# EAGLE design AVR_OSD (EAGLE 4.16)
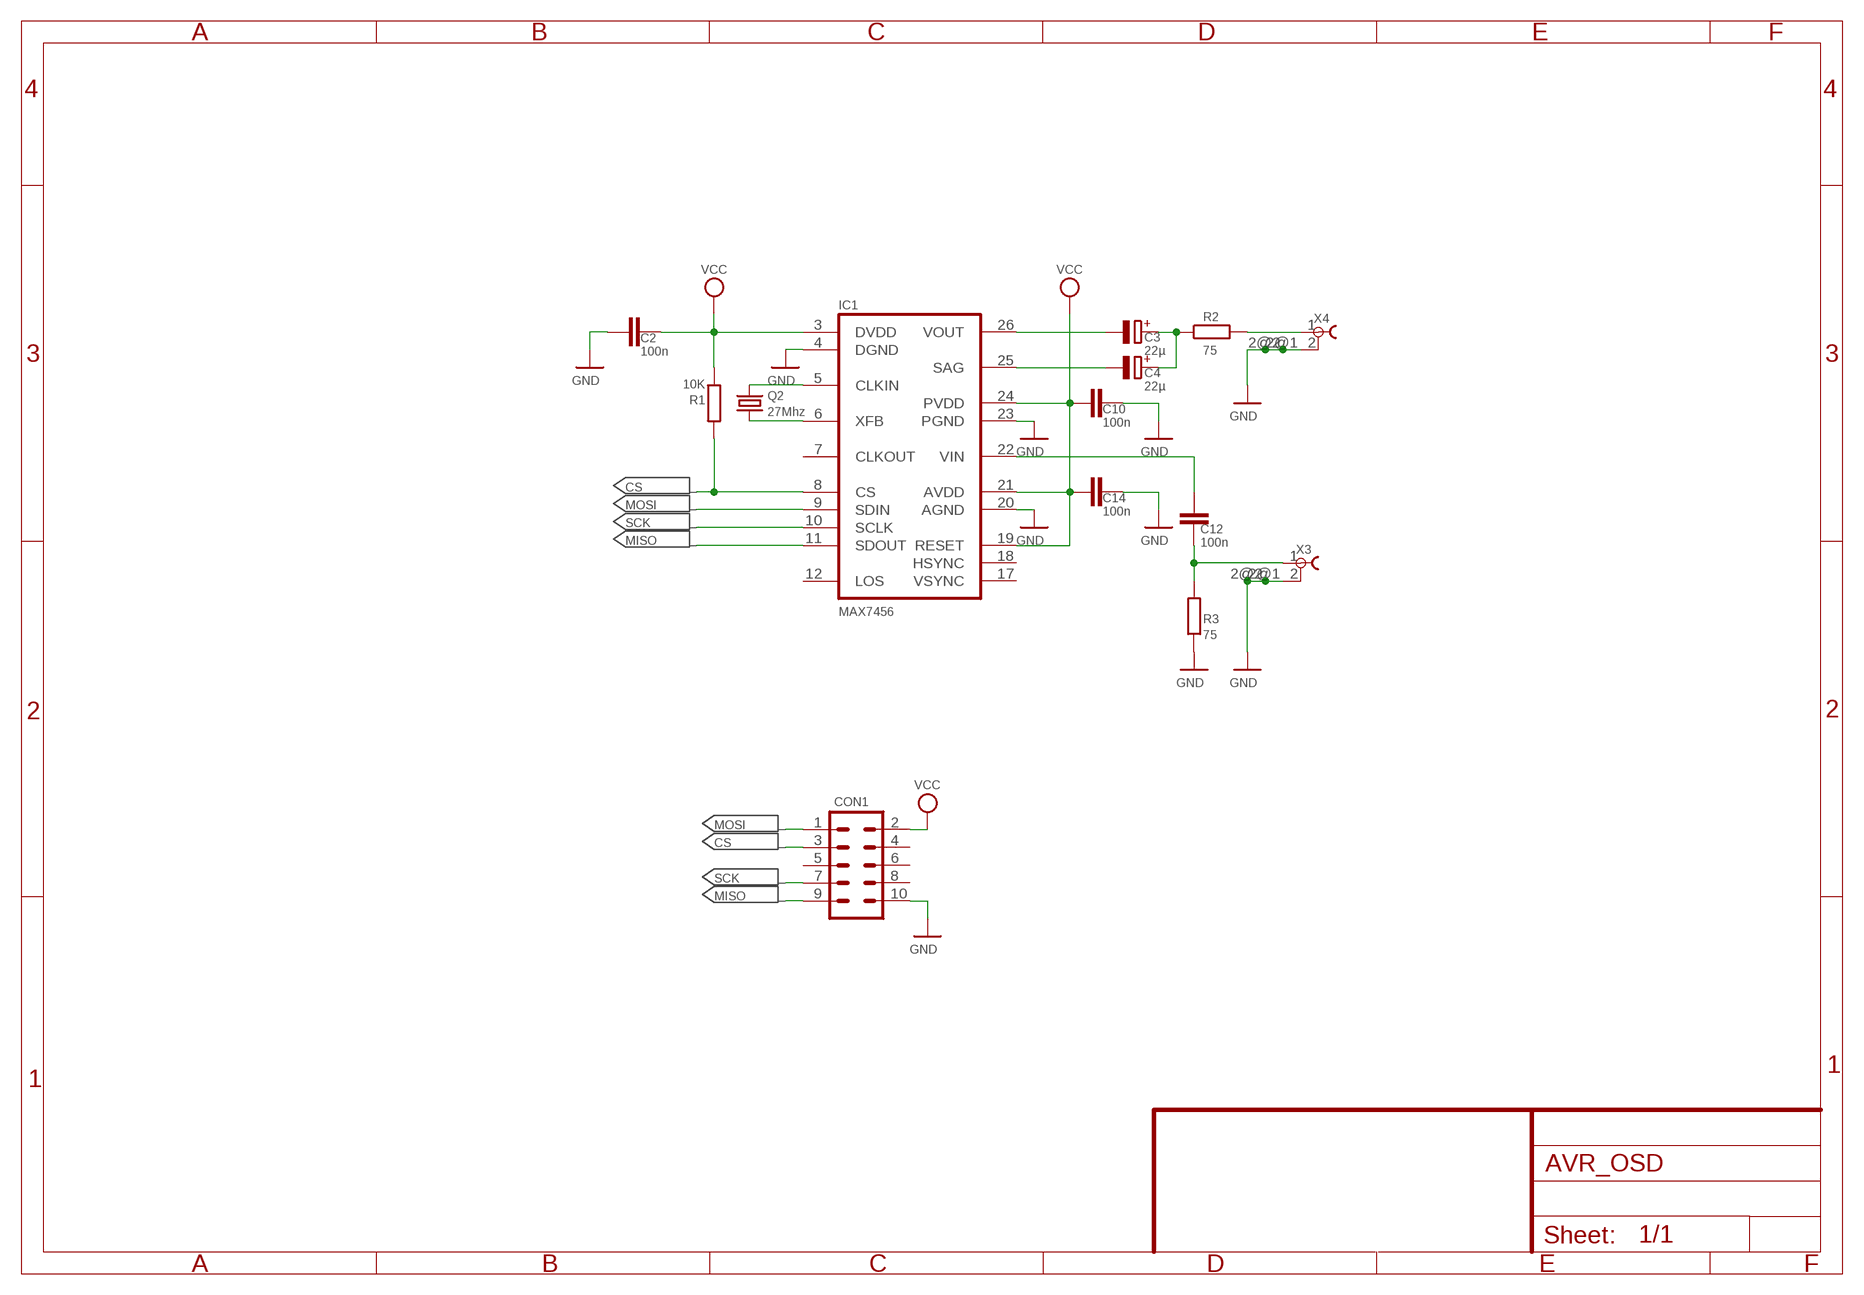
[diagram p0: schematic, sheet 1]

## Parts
C2  100n  C-EUC0805  [C0805]
C3  22µ  CPOL-EUSMCC  [SMC_C]
C4  22µ  CPOL-EUSMCC  [SMC_C]
C10  100n  C-EUC0805  [C0805]
C12  100n  C-EUC0805  [C0805]
C14  100n  C-EUC0805  [C0805]
CON1  ML10  [ML10]
IC1  MAX7456  [TSSOP28]
Q2  27Mhz  CRYSTALHC49S  [HC49/S]
R1  10K  R-EU_M0805  [M0805]
R2  75  R-EU_M0805  [M0805]
R3  75  R-EU_M0805  [M0805]
X3  TOBU3  [TOBU3]
X4  TOBU3  [TOBU3]

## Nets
CS: CON1.3 IC1.8(CS) R1.2
GND: C2.1 C10.2 C14.1 CON1.10 IC1.4(DGND) IC1.20(AGND) IC1.23(PGND) R3.1 X3.2 X3.2@1 X3.2@2 X4.2 X4.2@1 X4.2@2
MISO: CON1.9 IC1.11(SDOUT)
MOSI: CON1.1 IC1.9(SDIN)
N$24: C3.- IC1.26(VOUT)
N$27: C4.- IC1.25(SAG)
N$28: C3.+ C4.+ R2.1
N$29: R2.2 X4.1
N$30: C12.1 IC1.22(VIN)
N$33: C12.2 R3.2 X3.1
N$38: IC1.5(CLKIN) Q2.2
N$41: IC1.6(XFB) Q2.1
SCK: CON1.7 IC1.10(SCLK)
VCC: C2.2 C10.1 C14.2 CON1.2 IC1.3(DVDD) IC1.19(RESET) IC1.21(AVDD) IC1.24(PVDD) R1.1
Unconnected: CON1.4 CON1.5 CON1.6 CON1.8 IC1.7(CLKOUT) IC1.12(LOS) IC1.17(VSYNC) IC1.18(HSYNC)

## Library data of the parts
C2 C10 C12 C14 = rcl:C-EU: CAPACITOR, European symbol
C3 C4 = rcl:CPOL-EU: POLARIZED CAPACITOR, European symbol
CON1 = con-harting-ml:ML10: HARTING
IC1 = max7456:MAX7456
Q2 = crystal:CRYSTAL: CRYSTAL
R1-R3 = rcl:R-EU_: RESISTOR, European symbol
X3 X4 = con-hirschmann:TOBU3: Female Cinch CONNECTOR

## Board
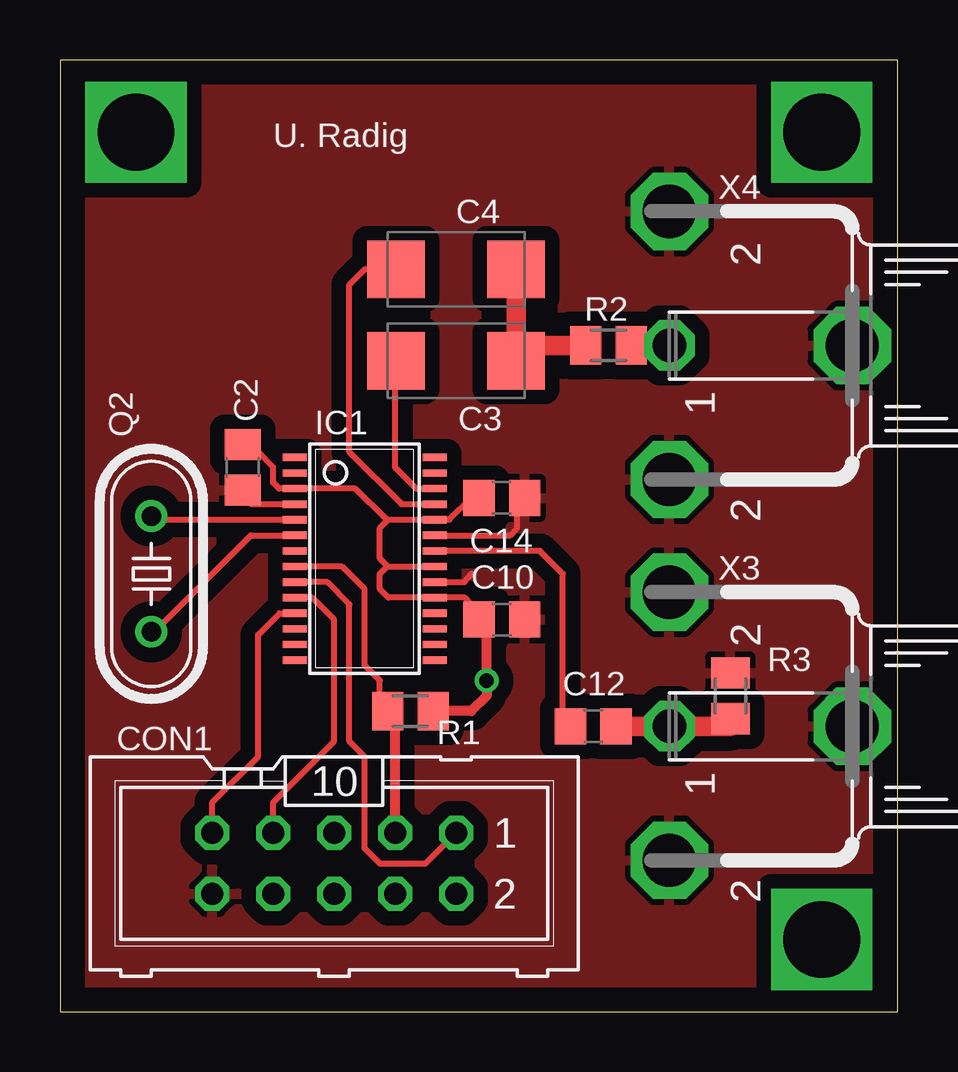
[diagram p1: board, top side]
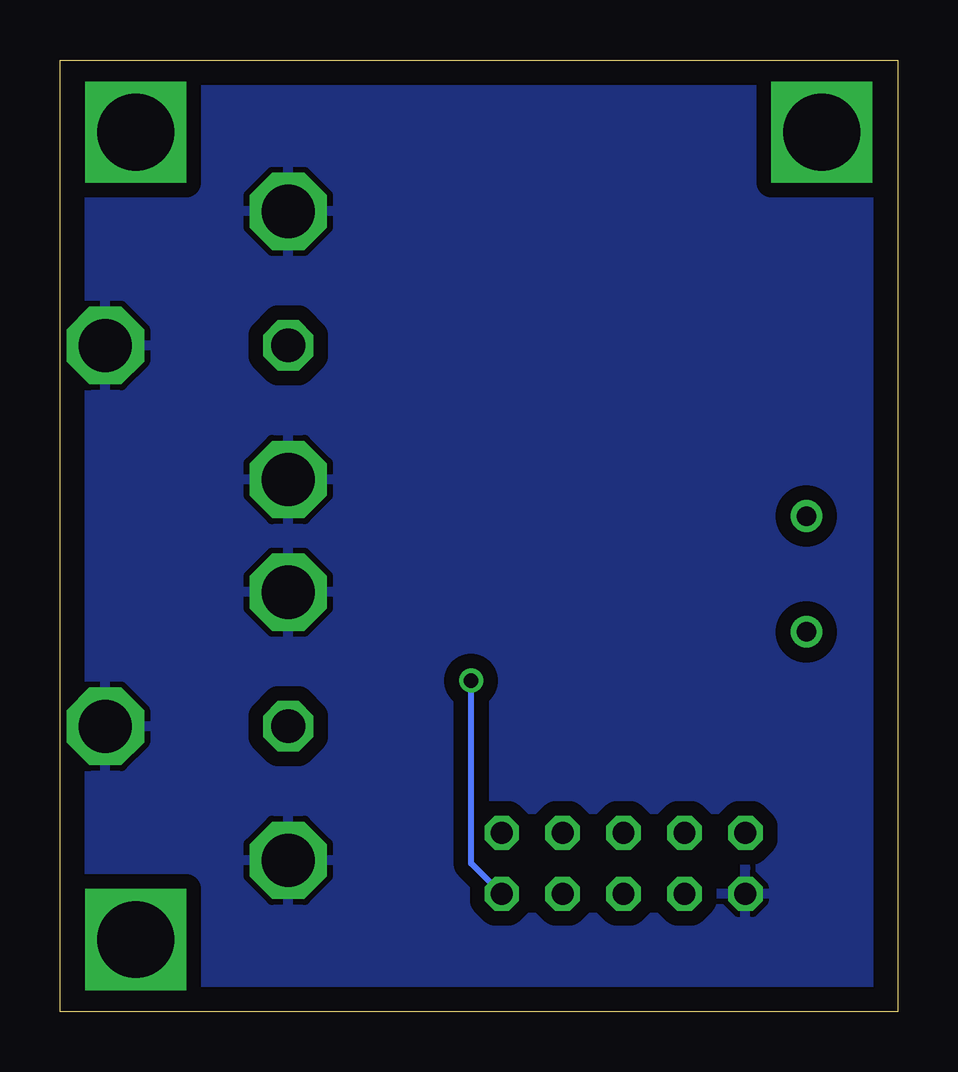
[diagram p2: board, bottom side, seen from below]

Size 34.9 x 39.68 mm. Coordinates in mm from the lower left corner, seen from the top.
Outline: 0,0 34.9,0 34.9,39.68 0,39.68 0,0
Copper layers (1*16): Top 0.035mm / dielectric 1.5mm / Bottom 0.035mm
Design rules "default": minimum track width 10mil, minimum drill 24mil, track to track 8mil, track to pad 8mil, pad to pad 8mil, via to via 8mil, smd to smd 8mil, copper to edge 40mil, drill to drill 8mil, minimum pad ring 10mil, minimum via ring 8mil, stop-mask expansion 4mil, vias tented up to drill 0mil, thermal gap 10mil

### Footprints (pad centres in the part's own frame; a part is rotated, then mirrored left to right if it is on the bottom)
C0805 = smd 1.3 x 1.5: 1 -0.95,0; 2 0.95,0
SMC_C = smd 2.4 x 2.4: + -2.5,0; - 2.5,0
ML10 = drill 0.914 octagon: 1 -5.08,-1.27; 2 -5.08,1.27; 3 -2.54,-1.27; 4 -2.54,1.27; 5 0,-1.27; 6 0,1.27; 7 2.54,-1.27; 8 2.54,1.27; 9 5.08,-1.27; 10 5.08,1.27
TSSOP28 = smd 0.305 x 0.991: 1 -4.225,-2.918; 2 -3.575,-2.918; 3 -2.925,-2.918; 4 -2.275,-2.918; 5 -1.625,-2.918; 6 -0.975,-2.918; 7 -0.325,-2.918; 8 0.325,-2.918; 9 0.975,-2.918; 10 1.625,-2.918; 11 2.275,-2.918; 12 2.925,-2.918; 13 3.575,-2.918; 14 4.225,-2.918; 15 4.225,2.918; 16 3.575,2.918; 17 2.925,2.918; 18 2.275,2.918; 19 1.625,2.918; 20 0.975,2.918; 21 0.325,2.918; 22 -0.325,2.918; 23 -0.975,2.918; 24 -1.625,2.918; 25 -2.275,2.918; 26 -2.925,2.918; 27 -3.575,2.918; 28 -4.225,2.918
HC49/S = drill 0.813 round: 1 -2.413,0; 2 2.413,0
M0805 = smd 1.3 x 1.6: 1 -0.95,0; 2 0.95,0
TOBU3 = drill 1.397 octagon: 1 0,-2.54 | drill 2.21 octagon: 2 5.588,-2.54; 2@1 -5.588,-2.54; 2@2 0,5.08

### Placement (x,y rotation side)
C2  7.62,22.7 90 top
C3  16.51,27.14 180 top
C4  16.51,30.95 180 top
C10  18.41,16.35 0 top
C12  22.22,11.9 0 top
C14  18.41,21.43 180 top
CON1  11.42,6.18 180 top
IC1  12.69,18.89 270 top
Q2  3.81,18.25 90 top
R1  14.6,12.54 180 top
R2  22.86,27.78 0 top
R3  27.94,13.17 270 top
X3  27.94,11.9 270 top
X4  27.94,27.78 270 top

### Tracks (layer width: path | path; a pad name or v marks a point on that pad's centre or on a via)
CS
  Top 0.254: 13.96,12.54 R1.2 13.33,12.54 13.33,13.81 12.69,14.44 12.69,17.62 11.75,18.56 IC1.8
  Top 0.406: CON1.3 13.96,12.54
GND
  Top 0.254: IC1.4 7.99,21.16 7.62,21.43 C2.1 7.62,22.06 | IC1.20 16.85,17.91 17.14,18.25 | IC1.23 18.75,19.86 19.05,20.16 19.05,21.43 C14.1
  pour Top (isolate 0.61): 0.63,39.2 34.28,39.2 34.28,0.47 0.63,0.47
  pour Bottom (isolate 0.61): 0.63,39.2 34.28,39.2 34.28,0.47 0.63,0.47
MISO
  Top 0.254: CON1.9 6.34,8.73 8.25,10.63 8.25,15.71 9.15,16.61 IC1.11
MOSI
  Top 0.254: IC1.9 11.13,17.91 12.06,16.98 12.06,11.27 12.69,10.63 12.69,6.82 13.33,6.18 15.23,6.18 CON1.1
N$9  (via drill 3.2)
  other vias: 31.75,36.66
N$23  (via drill 3.2)
  other vias: 31.75,3.01
N$24
  Top 0.254: IC1.26 14.85,21.81 13.96,22.7 13.96,26.51 C3.-
N$26  (via drill 3.2)
  other vias: 3.17,36.66
N$27
  Top 0.254: C4.- 12.69,30.95 12.06,30.32 12.06,23.33 14.23,21.16 IC1.25
N$28
  Top 0.813: R2.1 19.68,27.78 19.05,27.14 C3.+ 19.01,30.91 19.05,30.95 C4.+
N$29
  Top 0.406: R2.2 24.76,27.78
  Top 0.813: R2.2 X4.1
N$30
  Top 0.254: IC1.22 19.99,19.21 20.95,18.25 20.95,11.9 C12.1 21.59,11.9
N$33
  Top 0.254: 27.94,11.9 R3.2 27.62,12.22 27.94,11.9
  Top 0.813: X3.1 C12.2 X3.1 | X3.1 27.94,11.9
N$38
  Top 0.254: Q2.2 3.81,20.79 4.08,20.51 IC1.5
N$41
  Top 0.254: Q2.1 3.81,15.71 7.96,19.86 IC1.6
SCK
  Top 0.254: IC1.10 10.51,17.26 11.42,16.35 11.42,11.27 8.88,8.73 CON1.7
VCC  (via drill 0.6)
  Top 0.254: 13.68,20.51 13.61,20.51 12.31,21.81 IC1.3 9.13,21.81 8.88,22.06 8.88,22.7 8.25,23.33 7.62,23.33 C2.2 7.62,23.96 | 13.68,20.51 IC1.24 16.23,20.51 17.14,21.43 C14.2 | 13.68,20.51 13.33,20.16 13.33,18.89 13.65,18.56 | 13.65,18.56 IC1.21 | 13.65,18.56 13.64,18.56 13.33,18.25 13.33,17.62 13.68,17.26 IC1.19 16.86,17.26 17.14,16.98 | 17.14,16.98 C10.1 | 17.78,16.35 17.14,16.98
  Top 0.406: 17.78,16.35 v17.78,13.81 17.78,13.17 17.14,12.54 R1.1
  Bottom 0.254: CON1.2 17.78,6.18 v17.78,13.81

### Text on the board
tPlace: U. Radig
